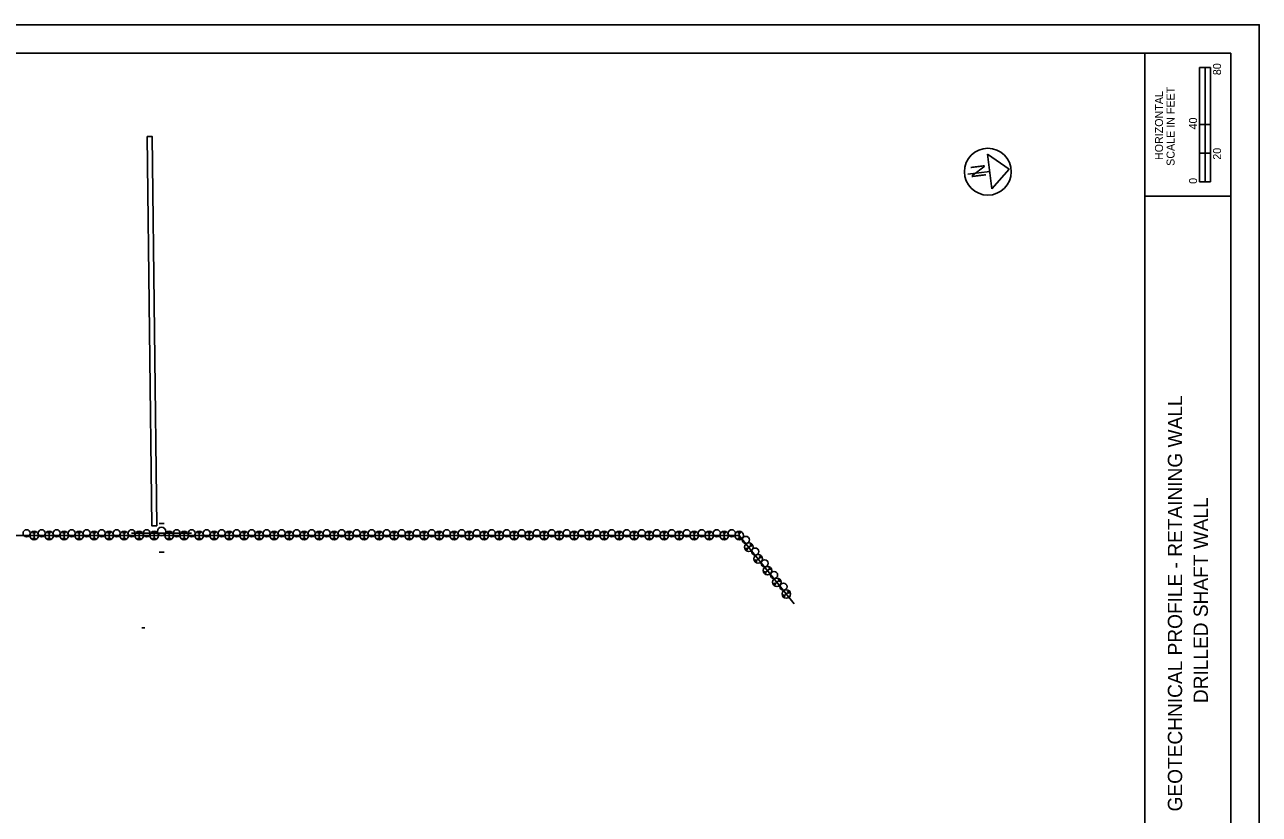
# Model space of a CAD drawing. Extents: x -2280229 to 1306, y -58886 to 440.
# Drawn here: x 248 to 680, y 163.6 to 440 of the extents above; entities that cross this region are included whole.
import ezdxf

# ---------------------------------------------------------------- set-up
doc = ezdxf.new("R2010")
doc.units = 0
for name, color, linetype in [('BR_P_Beam_Stl_Det', 7, 'Continuous'), ('BR_P_Det_Object', 7, 'Continuous'), ('BR_P_Gen_Centerline', 7, 'Continuous'), ('BR_P_Sub_Deep_Object', 7, 'Continuous'), ('DR_X_Storm_Sewer', 7, 'Continuous'), ('DR_X_Underdrain', 7, 'Continuous'), ('GT_Project_Cells', 7, 'Continuous'), ('GT_Project_Text', 7, 'Continuous'), ('GT_Project_Text_2', 7, 'Continuous'), ('SC_Scratch1', 7, 'Continuous'), ('SC_Scratch6', 7, 'Continuous'), ('SC_Scratch9', 7, 'Continuous')]:
    doc.layers.add(name, color=color, linetype=linetype)

msp = doc.modelspace()

# ---------------------------------------------------------------- linework, layer by layer
at = {"layer": 'BR_P_Beam_Stl_Det'}
for p, q in [((250.74, 262.15), (251.82, 262.15)), ((250.74, 260.11), (251.82, 260.11)), ((251.28, 262.15), (251.28, 260.11)), ((255.99, 262.15), (257.07, 262.15)), ((255.99, 260.11), (257.07, 260.11)), ((256.53, 262.15), (256.53, 260.11)), ((261.24, 262.15), (262.32, 262.15)), ((261.24, 260.11), (262.32, 260.11)), ((261.78, 262.15), (261.78, 260.11)), ((266.49, 262.15), (267.57, 262.15)), ((266.49, 260.11), (267.57, 260.11)), ((267.03, 262.15), (267.03, 260.11)), ((271.74, 262.15), (272.82, 262.15)), ((271.74, 260.11), (272.82, 260.11)), ((272.28, 262.15), (272.28, 260.11)), ((276.99, 262.15), (278.07, 262.15)), ((276.99, 260.11), (278.07, 260.11)), ((277.53, 262.15), (277.53, 260.11)), ((282.24, 262.15), (283.32, 262.15)), ((282.24, 260.11), (283.32, 260.11)), ((282.78, 262.15), (282.78, 260.11)), ((287.49, 262.15), (288.57, 262.15)), ((287.49, 260.11), (288.57, 260.11)), ((288.03, 262.15), (288.03, 260.11)), ((292.74, 262.15), (293.82, 262.15)), ((292.74, 260.11), (293.82, 260.11)), ((293.28, 262.15), (293.28, 260.11)), ((297.99, 262.15), (299.07, 262.15)), ((297.99, 260.11), (299.07, 260.11)), ((298.53, 262.15), (298.53, 260.11)), ((303.24, 262.15), (304.32, 262.15)), ((303.24, 260.11), (304.32, 260.11)), ((303.78, 262.15), (303.78, 260.11)), ((308.49, 262.15), (309.57, 262.15)), ((308.49, 260.11), (309.57, 260.11)), ((309.03, 262.15), (309.03, 260.11)), ((313.74, 262.15), (314.82, 262.15)), ((313.74, 260.11), (314.82, 260.11)), ((314.28, 262.15), (314.28, 260.11)), ((318.99, 262.15), (320.07, 262.15)), ((318.99, 260.11), (320.07, 260.11)), ((319.53, 262.15), (319.53, 260.11)), ((324.24, 262.15), (325.32, 262.15)), ((324.24, 260.11), (325.32, 260.11)), ((324.78, 262.15), (324.78, 260.11)), ((329.49, 262.15), (330.57, 262.15)), ((329.49, 260.11), (330.57, 260.11)), ((330.03, 262.15), (330.03, 260.11)), ((334.74, 262.15), (335.82, 262.15)), ((334.74, 260.11), (335.82, 260.11)), ((335.28, 262.15), (335.28, 260.11)), ((339.99, 262.15), (341.07, 262.15)), ((339.99, 260.11), (341.07, 260.11)), ((340.53, 262.15), (340.53, 260.11)), ((345.24, 262.15), (346.32, 262.15)), ((345.24, 260.11), (346.32, 260.11)), ((345.78, 262.15), (345.78, 260.11)), ((350.49, 262.15), (351.57, 262.15)), ((350.49, 260.11), (351.57, 260.11)), ((351.03, 262.15), (351.03, 260.11)), ((355.74, 262.15), (356.82, 262.15)), ((355.74, 260.11), (356.82, 260.11)), ((356.28, 262.15), (356.28, 260.11)), ((360.99, 262.15), (362.07, 262.15)), ((360.99, 260.11), (362.07, 260.11)), ((361.53, 262.15), (361.53, 260.11)), ((366.24, 262.15), (367.32, 262.15)), ((366.24, 260.11), (367.32, 260.11)), ((366.78, 262.15), (366.78, 260.11)), ((371.49, 262.15), (372.57, 262.15)), ((371.49, 260.11), (372.57, 260.11)), ((372.03, 262.15), (372.03, 260.11)), ((376.74, 262.15), (377.82, 262.15)), ((376.74, 260.11), (377.82, 260.11)), ((377.28, 262.15), (377.28, 260.11)), ((381.99, 262.15), (383.07, 262.15)), ((381.99, 260.11), (383.07, 260.11)), ((382.53, 262.15), (382.53, 260.11)), ((387.24, 262.15), (388.32, 262.15)), ((387.24, 260.11), (388.32, 260.11)), ((387.78, 262.15), (387.78, 260.11)), ((392.49, 262.15), (393.57, 262.15)), ((392.49, 260.11), (393.57, 260.11)), ((393.03, 262.15), (393.03, 260.11)), ((397.74, 262.15), (398.82, 262.15)), ((397.74, 260.11), (398.82, 260.11)), ((398.28, 262.15), (398.28, 260.11)), ((402.99, 262.15), (404.07, 262.15)), ((402.99, 260.11), (404.07, 260.11)), ((403.53, 262.15), (403.53, 260.11)), ((408.24, 262.15), (409.32, 262.15)), ((408.24, 260.11), (409.32, 260.11)), ((408.78, 262.15), (408.78, 260.11)), ((413.49, 262.15), (414.57, 262.15)), ((413.49, 260.11), (414.57, 260.11)), ((414.03, 262.15), (414.03, 260.11)), ((418.74, 262.15), (419.82, 262.15)), ((418.74, 260.11), (419.82, 260.11)), ((419.28, 262.15), (419.28, 260.11)), ((423.99, 262.15), (425.07, 262.15)), ((423.99, 260.11), (425.07, 260.11)), ((424.53, 262.15), (424.53, 260.11)), ((429.24, 262.15), (430.32, 262.15)), ((429.24, 260.11), (430.32, 260.11)), ((429.78, 262.15), (429.78, 260.11)), ((434.49, 262.15), (435.57, 262.15)), ((434.49, 260.11), (435.57, 260.11)), ((435.03, 262.15), (435.03, 260.11)), ((439.74, 262.15), (440.82, 262.15)), ((439.74, 260.11), (440.82, 260.11)), ((440.28, 262.15), (440.28, 260.11)), ((444.99, 262.15), (446.07, 262.15)), ((444.99, 260.11), (446.07, 260.11)), ((445.53, 262.15), (445.53, 260.11)), ((450.24, 262.15), (451.32, 262.15)), ((450.24, 260.11), (451.32, 260.11)), ((450.78, 262.15), (450.78, 260.11)), ((455.49, 262.15), (456.57, 262.15)), ((455.49, 260.11), (456.57, 260.11)), ((456.03, 262.15), (456.03, 260.11)), ((460.74, 262.15), (461.82, 262.15)), ((460.74, 260.11), (461.82, 260.11)), ((461.28, 262.15), (461.28, 260.11)), ((465.99, 262.15), (467.07, 262.15)), ((465.99, 260.11), (467.07, 260.11)), ((466.53, 262.15), (466.53, 260.11)), ((471.24, 262.15), (472.32, 262.15)), ((471.24, 260.11), (472.32, 260.11)), ((471.78, 262.15), (471.78, 260.11)), ((476.49, 262.15), (477.57, 262.15)), ((476.49, 260.11), (477.57, 260.11)), ((477.03, 262.15), (477.03, 260.11)), ((481.74, 262.15), (482.82, 262.15)), ((481.74, 260.11), (482.82, 260.11)), ((482.28, 262.15), (482.28, 260.11)), ((486.99, 262.15), (488.07, 262.15)), ((486.99, 260.11), (488.07, 260.11)), ((487.53, 262.15), (487.53, 260.11)), ((492.24, 262.15), (493.32, 262.15)), ((492.24, 260.11), (493.32, 260.11)), ((492.78, 262.15), (492.78, 260.11)), ((497.49, 262.15), (498.57, 262.15)), ((497.49, 260.11), (498.57, 260.11)), ((498.03, 262.15), (498.03, 260.11)), ((500.21, 256.84), (500.88, 256)), ((502.14, 257.7), (500.55, 256.42)), ((501.8, 258.12), (502.48, 257.28)), ((503.5, 252.75), (504.17, 251.91)), ((505.43, 253.61), (503.84, 252.33)), ((505.09, 254.03), (505.76, 253.19)), ((506.79, 248.65), (507.46, 247.82)), ((508.71, 249.51), (507.12, 248.24)), ((508.38, 249.93), (509.05, 249.1)), ((510.07, 244.56), (510.75, 243.72)), ((512, 245.42), (510.41, 244.14)), ((511.67, 245.84), (512.34, 245)), ((513.36, 240.47), (514.03, 239.63)), ((515.29, 241.33), (513.7, 240.05)), ((514.95, 241.75), (515.63, 240.91))]:
    msp.add_line(p, q, dxfattribs=at)
at = {"layer": 'BR_P_Det_Object'}
for p, q in [((295.02, 265.31), (296.77, 265.31)), ((295.03, 255.31), (296.78, 255.31))]:
    msp.add_line(p, q, dxfattribs=at)
at = {"layer": 'BR_P_Gen_Centerline'}
for p, q in [((119.75, 261.13), (498.03, 261.13)), ((498.03, 261.13), (517.23, 237.29))]:
    msp.add_line(p, q, dxfattribs=at)
at = {"layer": 'BR_P_Sub_Deep_Object'}
for centre, radius in [((295.9, 262.57), 1.5), ((248.66, 261.94), 1.25), ((251.28, 261.13), 1.5), ((253.91, 261.94), 1.25), ((256.53, 261.13), 1.5), ((259.16, 261.94), 1.25), ((261.78, 261.13), 1.5), ((264.41, 261.94), 1.25), ((267.03, 261.13), 1.5), ((269.66, 261.94), 1.25), ((272.28, 261.13), 1.5), ((274.91, 261.94), 1.25), ((277.53, 261.13), 1.5), ((280.16, 261.94), 1.25), ((282.78, 261.13), 1.5), ((285.41, 261.94), 1.25), ((288.03, 261.13), 1.5), ((290.66, 261.94), 1.25), ((293.28, 261.13), 1.5), ((298.53, 261.13), 1.5), ((301.16, 261.94), 1.25), ((303.78, 261.13), 1.5), ((306.41, 261.94), 1.25), ((309.03, 261.13), 1.5), ((311.66, 261.94), 1.25), ((314.28, 261.13), 1.5), ((316.91, 261.94), 1.25), ((319.53, 261.13), 1.5), ((322.16, 261.94), 1.25), ((324.78, 261.13), 1.5), ((327.41, 261.94), 1.25), ((330.03, 261.13), 1.5), ((332.66, 261.94), 1.25), ((335.28, 261.13), 1.5), ((337.91, 261.94), 1.25), ((340.53, 261.13), 1.5), ((343.16, 261.94), 1.25), ((345.78, 261.13), 1.5), ((348.41, 261.94), 1.25), ((351.03, 261.13), 1.5), ((353.66, 261.94), 1.25), ((356.28, 261.13), 1.5), ((358.91, 261.94), 1.25), ((361.53, 261.13), 1.5), ((364.16, 261.94), 1.25), ((366.78, 261.13), 1.5), ((369.41, 261.94), 1.25), ((372.03, 261.13), 1.5), ((374.66, 261.94), 1.25), ((377.28, 261.13), 1.5), ((379.91, 261.94), 1.25), ((382.53, 261.13), 1.5), ((385.16, 261.94), 1.25), ((387.78, 261.13), 1.5), ((390.41, 261.94), 1.25), ((393.03, 261.13), 1.5), ((395.66, 261.94), 1.25), ((398.28, 261.13), 1.5), ((400.91, 261.94), 1.25), ((403.53, 261.13), 1.5), ((406.16, 261.94), 1.25), ((408.78, 261.13), 1.5), ((411.41, 261.94), 1.25), ((414.03, 261.13), 1.5), ((416.66, 261.94), 1.25), ((419.28, 261.13), 1.5), ((421.91, 261.94), 1.25), ((424.53, 261.13), 1.5), ((427.16, 261.94), 1.25), ((429.78, 261.13), 1.5), ((432.41, 261.94), 1.25), ((435.03, 261.13), 1.5), ((437.66, 261.94), 1.25), ((440.28, 261.13), 1.5), ((442.91, 261.94), 1.25), ((445.53, 261.13), 1.5), ((448.16, 261.94), 1.25), ((450.78, 261.13), 1.5), ((453.41, 261.94), 1.25), ((456.03, 261.13), 1.5), ((458.66, 261.94), 1.25), ((461.28, 261.13), 1.5), ((463.91, 261.94), 1.25), ((466.53, 261.13), 1.5), ((469.16, 261.94), 1.25), ((471.78, 261.13), 1.5), ((474.41, 261.94), 1.25), ((477.03, 261.13), 1.5), ((479.66, 261.94), 1.25), ((482.28, 261.13), 1.5), ((484.91, 261.94), 1.25), ((487.53, 261.13), 1.5), ((490.16, 261.94), 1.25), ((492.78, 261.13), 1.5), ((495.41, 261.94), 1.25), ((498.03, 261.13), 1.5), ((500.34, 259.62), 1.25), ((501.34, 257.06), 1.5), ((503.62, 255.53), 1.25), ((504.63, 252.97), 1.5), ((506.91, 251.43), 1.25), ((507.92, 248.87), 1.5), ((510.2, 247.34), 1.25), ((511.21, 244.78), 1.5), ((513.49, 243.25), 1.25), ((514.49, 240.69), 1.5)]:
    msp.add_circle(centre, radius, dxfattribs=at)
at = {"layer": 'DR_X_Storm_Sewer'}
msp.add_line((290.87, 400.8), (292.62, 400.8), dxfattribs=at)
msp.add_lwpolyline([(290.87, 400.8), (292.42, 264.55), (294.17, 264.57), (292.62, 400.8)], close=True, dxfattribs=at)
at = {"layer": 'DR_X_Underdrain'}
msp.add_line((290, 228.81), (289, 228.81), dxfattribs=at)
at = {"layer": 'GT_Project_Cells'}
for p, q in [((659.13, 385), (659.13, 425)), ((662.88, 425), (659.13, 425)), ((659.13, 405), (659.13, 425)), ((659.13, 425), (661, 425)), ((661, 425), (661.02, 425)), ((661.02, 425), (661.02, 405)), ((662.88, 425), (662.88, 385)), ((661.02, 405), (659.13, 405)), ((662.87, 405), (661, 405)), ((661, 405), (661, 395)), ((662.87, 395), (662.87, 405)), ((661, 395), (659.13, 395)), ((659.13, 395), (659.13, 385)), ((661, 385), (661, 395)), ((661, 395), (662.87, 395)), ((662.88, 385), (659.13, 385)), ((659.13, 385), (661, 385))]:
    msp.add_line(p, q, dxfattribs=at)
at = {"layer": 'GT_Project_Text'}
msp.add_lwpolyline([(0, 0), (680, 0), (680, 440), (0, 440)], close=True, dxfattribs=at)
at = {"layer": 'GT_Project_Text_2'}
msp.add_circle((585.02, 388.52), 8.2, dxfattribs=at)
at = {"layer": 'SC_Scratch1'}
for p, q in [((640, 10), (640, 430)), ((640, 380), (670, 380))]:
    msp.add_line(p, q, dxfattribs=at)
msp.add_lwpolyline([(30, 430), (670, 430), (670, 10), (30, 10)], close=True, dxfattribs=at)
at = {"layer": 'SC_Scratch6'}
for p, q in [((592.44, 389.43), (584.92, 394.71)), ((584.92, 394.71), (586.42, 382.49)), ((586.42, 382.49), (592.44, 389.43)), ((585.67, 388.6), (577.99, 387.66))]:
    msp.add_line(p, q, dxfattribs=at)
msp.add_circle((585.02, 388.52), 8.2, dxfattribs=at)
at = {"layer": 'SC_Scratch9'}
msp.add_line((285.41, 261.94), (306.41, 261.94), dxfattribs=at)

# ---------------------------------------------------------------- texts
at = {"layer": 'GT_Project_Cells'}
for s, height, p in [('80', 2.8, (666.61, 422.33)), ('HORIZONTAL', 2.8, (646.3, 392.61)), ('SCALE IN FEET', 2.8, (650.35, 390.58)), ('40', 2.8, (658.21, 403.33)), ('20', 2.8, (666.61, 392.73)), ('0', 2.8, (658.21, 384.27)), ('GEOTECHNICAL PROFILE - RETAINING WALL', 5, (653, 164.56)), ('DRILLED SHAFT WALL', 5, (662, 202.47))]:
    msp.add_text(s, height=height, rotation=90, dxfattribs=at).set_placement(p)
at = {"layer": 'SC_Scratch6'}
msp.add_text('N', height=5, rotation=276.9843, dxfattribs=at).set_placement((578.87, 390.82))

doc.saveas('drawing.dxf')
